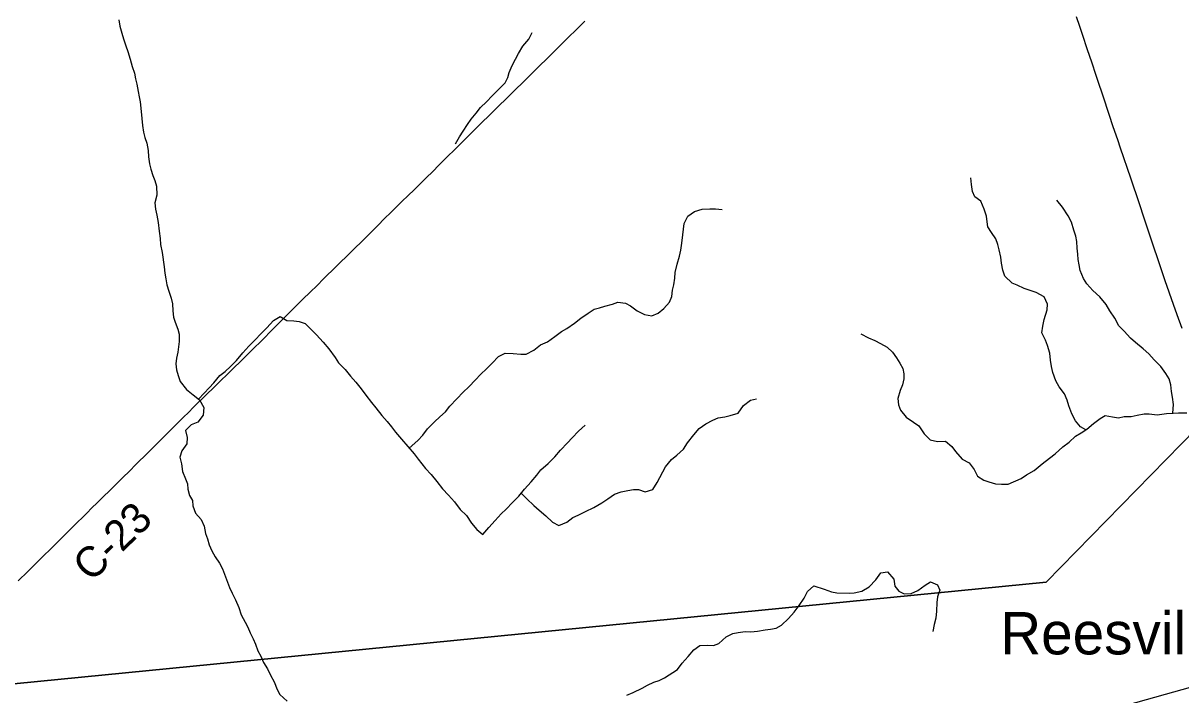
# Model space of a CAD drawing. Extents: x 1442749 to 1756758, y 235267 to 677782.
# Drawn here: x 1623834 to 1635226, y 541852 to 548463 of the extents above; entities that cross this region are included whole.
import ezdxf

# ---------------------------------------------------------------- set-up
doc = ezdxf.new("R2010")
doc.units = 0
for name, color, linetype in [('GM_X_County_Road', 7, 'Continuous'), ('GM_X_County_Road_Text', 7, 'Continuous'), ('GM_X_Major_River', 7, 'Continuous'), ('GM_X_Minor_River', 7, 'Continuous'), ('GM_X_Rail_Line', 7, 'Continuous'), ('GM_X_State_Route', 7, 'Continuous'), ('GM_X_Township', 7, 'Continuous'), ('GM_X_Unincorporated_Text', 7, 'Continuous')]:
    doc.layers.add(name, color=color, linetype=linetype)

msp = doc.modelspace()

# ---------------------------------------------------------------- linework, layer by layer
at = {"layer": 'GM_X_County_Road'}
msp.add_lwpolyline([(1623785, 542973), (1623880, 543067), (1623962, 543148), (1624174, 543358), (1624323, 543506), (1624463, 543644), (1624508, 543689), (1624565, 543744), (1624625, 543803), (1624683, 543861), (1624746, 543922), (1624816, 543991), (1624879, 544054), (1624944, 544118), (1625062, 544234), (1625147, 544319), (1625226, 544398), (1625293, 544466), (1625339, 544513), (1625406, 544578), (1625468, 544639), (1625505, 544676), (1625547, 544718), (1625599, 544768), (1625643, 544811), (1625706, 544873), (1625763, 544929), (1625857, 545021), (1625912, 545075), (1625969, 545131), (1626015, 545176), (1626061, 545222), (1626107, 545267), (1626169, 545328), (1626304, 545465), (1626497, 545657), (1626586, 545745), (1626657, 545814), (1626726, 545882), (1626791, 545946), (1626915, 546069), (1627202, 546351), (1627287, 546436), (1627336, 546485), (1627377, 546526), (1627466, 546613), (1627552, 546697), (1627631, 546775), (1627671, 546814), (1627707, 546850), (1627761, 546902), (1627808, 546948), (1627858, 546997), (1627932, 547071), (1628010, 547149), (1628078, 547216), (1628164, 547300), (1628316, 547451), (1628454, 547587), (1628651, 547781), (1628781, 547910), (1628871, 548000), (1629029, 548153), (1629082, 548206), (1629125, 548249), (1629161, 548285), (1629188, 548312), (1629217, 548340), (1629259, 548381), (1629305, 548426), (1629335, 548456), (1629361, 548483)], dxfattribs=at)
at = {"layer": 'GM_X_Major_River'}
for points in [[(1624774, 548496), (1624784, 548434), (1624805, 548365), (1624821, 548307), (1624845, 548241), (1624863, 548183), (1624888, 548108), (1624906, 548036), (1624928, 547970), (1624939, 547916), (1624953, 547862), (1624967, 547789), (1624976, 547737), (1624984, 547687), (1624996, 547593), (1625001, 547523), (1625007, 547455), (1625017, 547391), (1625030, 547338), (1625050, 547282), (1625064, 547208), (1625067, 547146), (1625077, 547078), (1625091, 547026), (1625110, 546965), (1625130, 546915), (1625146, 546859), (1625149, 546769), (1625129, 546693), (1625135, 546633), (1625148, 546574), (1625162, 546502), (1625174, 546416), (1625181, 546342), (1625187, 546286), (1625202, 546204), (1625222, 546063), (1625229, 546003), (1625237, 545947), (1625249, 545889), (1625266, 545825), (1625290, 545756), (1625302, 545702), (1625308, 545632), (1625315, 545570), (1625331, 545520), (1625355, 545451), (1625368, 545401), (1625370, 545329), (1625357, 545225), (1625343, 545165), (1625337, 545109), (1625342, 545051), (1625358, 544995), (1625378, 544936), (1625442, 544856), (1625507, 544806), (1625569, 544755), (1625613, 544681), (1625605, 544603), (1625552, 544537), (1625486, 544511), (1625431, 544455), (1625447, 544385), (1625445, 544321), (1625394, 544255), (1625376, 544191), (1625391, 544125), (1625403, 544049), (1625433, 543979), (1625450, 543928), (1625456, 543876), (1625470, 543814), (1625500, 543764), (1625505, 543712), (1625531, 543641), (1625587, 543579), (1625614, 543511), (1625628, 543441), (1625648, 543388), (1625664, 543330), (1625689, 543268), (1625723, 543210), (1625767, 543147), (1625795, 543093), (1625816, 543041), (1625846, 542961), (1625866, 542908), (1625890, 542852), (1625923, 542786), (1625955, 542712), (1625979, 542641), (1626018, 542567), (1626044, 542517), (1626068, 542463), (1626098, 542402), (1626119, 542352), (1626143, 542286), (1626173, 542232)], [(1626173, 542232), (1626198, 542170), (1626238, 542109), (1626268, 542047), (1626304, 541981), (1626335, 541904), (1626359, 541854), (1626431, 541790)]]:
    msp.add_lwpolyline(points, dxfattribs=at)
at = {"layer": 'GM_X_Minor_River'}
for points in [[(1628089, 547276), (1628128, 547345), (1628163, 547399), (1628208, 547465), (1628243, 547519), (1628292, 547578), (1628336, 547632), (1628395, 547687), (1628450, 547747), (1628501, 547800), (1628578, 547874), (1628603, 547928), (1628616, 547978), (1628645, 548046), (1628680, 548109), (1628709, 548165), (1628752, 548235), (1628811, 548306), (1628844, 548372)], [(1634291, 544460), (1634239, 544491), (1634189, 544549), (1634154, 544618), (1634123, 544695), (1634109, 544753), (1634080, 544815), (1634029, 544884), (1633995, 544943), (1633966, 545025), (1633955, 545082), (1633945, 545146), (1633936, 545216), (1633913, 545289), (1633894, 545343), (1633858, 545416), (1633869, 545480), (1633882, 545546), (1633911, 545640), (1633914, 545698), (1633881, 545768), (1633801, 545811), (1633733, 545834), (1633683, 545851), (1633617, 545884), (1633565, 545904), (1633495, 545973), (1633476, 546032), (1633463, 546102), (1633455, 546160), (1633440, 546231), (1633425, 546285), (1633407, 546339), (1633362, 546404), (1633326, 546457), (1633319, 546507), (1633314, 546563), (1633290, 546631), (1633259, 546712), (1633199, 546753), (1633176, 546807), (1633167, 546876), (1633160, 546942)], [(1627634, 544279), (1627718, 544355), (1627767, 544407), (1627814, 544469), (1627883, 544538), (1627934, 544588), (1627989, 544639), (1628032, 544693), (1628101, 544764), (1628164, 544830), (1628221, 544885), (1628286, 544951), (1628333, 545004), (1628396, 545064), (1628449, 545115), (1628512, 545181), (1628578, 545214), (1628657, 545211), (1628731, 545204), (1628783, 545204), (1628860, 545243), (1628925, 545297), (1628994, 545326), (1629067, 545379), (1629133, 545427), (1629184, 545458), (1629259, 545511), (1629322, 545559), (1629393, 545610), (1629453, 545648), (1629504, 545661), (1629558, 545677), (1629633, 545696), (1629687, 545717), (1629760, 545708), (1629811, 545680), (1629875, 545631), (1629949, 545594), (1630021, 545583), (1630084, 545608), (1630137, 545654), (1630194, 545718), (1630216, 545771), (1630225, 545834), (1630236, 545886), (1630247, 545952), (1630249, 546010), (1630270, 546092), (1630293, 546168), (1630306, 546228), (1630317, 546298), (1630326, 546380), (1630333, 546434), (1630340, 546492), (1630375, 546562), (1630441, 546609), (1630516, 546633), (1630590, 546634), (1630647, 546637), (1630713, 546630)], [(1635149, 544625), (1635154, 544709), (1635144, 544781), (1635135, 544836), (1635128, 544902), (1635110, 544962), (1635079, 545015), (1635030, 545082), (1634964, 545148), (1634910, 545207), (1634855, 545258), (1634781, 545319), (1634730, 545364), (1634668, 545431), (1634617, 545483), (1634577, 545558), (1634528, 545631), (1634490, 545693), (1634429, 545768), (1634360, 545833), (1634300, 545898), (1634269, 545949), (1634235, 546029), (1634226, 546083), (1634217, 546136), (1634211, 546188), (1634206, 546248), (1634203, 546314), (1634193, 546365), (1634174, 546427), (1634151, 546503), (1634117, 546566), (1634062, 546651), (1634005, 546720)], [(1625560, 544763), (1625615, 544820), (1625665, 544872), (1625710, 544924), (1625769, 544995), (1625822, 545035), (1625873, 545084), (1625934, 545142), (1625997, 545217), (1626056, 545283), (1626121, 545350), (1626170, 545402), (1626231, 545465), (1626298, 545535), (1626363, 545576), (1626429, 545535), (1626499, 545534), (1626549, 545528), (1626609, 545507), (1626665, 545450), (1626722, 545396), (1626786, 545323), (1626843, 545258), (1626903, 545173), (1626938, 545120), (1627002, 545055), (1627055, 544989), (1627109, 544930), (1627160, 544863), (1627205, 544802), (1627261, 544728), (1627306, 544677), (1627364, 544602), (1627415, 544543), (1627459, 544491), (1627498, 544438), (1627556, 544369), (1627619, 544296), (1627681, 544223), (1627722, 544171), (1627793, 544080), (1627849, 544019), (1627904, 543952), (1627960, 543881), (1628019, 543817), (1628079, 543750), (1628136, 543677), (1628198, 543618), (1628247, 543543), (1628298, 543480), (1628358, 543430), (1628417, 543499), (1628478, 543569), (1628537, 543632), (1628588, 543680), (1628651, 543745), (1628712, 543809), (1628769, 543876), (1628832, 543950), (1628889, 544013), (1628928, 544067), (1629001, 544130), (1629066, 544196), (1629121, 544261), (1629190, 544331), (1629237, 544382), (1629300, 544446), (1629365, 544507)], [(1632078, 545406), (1632152, 545367), (1632216, 545338), (1632272, 545311), (1632336, 545274), (1632389, 545226), (1632427, 545169), (1632460, 545118), (1632492, 545064), (1632499, 545012), (1632499, 544962), (1632488, 544902), (1632465, 544848), (1632442, 544770), (1632449, 544707), (1632467, 544653), (1632524, 544586), (1632594, 544537), (1632648, 544499), (1632699, 544420), (1632759, 544361), (1632833, 544344), (1632911, 544349), (1632973, 544296), (1633008, 544246), (1633074, 544173), (1633142, 544134), (1633193, 544069), (1633226, 544005), (1633286, 543964), (1633336, 543947), (1633404, 543930), (1633461, 543926), (1633527, 543927), (1633654, 543982), (1633707, 544017), (1633782, 544059), (1633861, 544124), (1633934, 544183), (1633991, 544223), (1634064, 544294), (1634127, 544340), (1634188, 544397), (1634246, 544430), (1634301, 544466), (1634368, 544521), (1634431, 544573), (1634483, 544600), (1634553, 544587), (1634612, 544579), (1634668, 544590), (1634736, 544593), (1634797, 544605), (1634865, 544618), (1634915, 544618), (1634994, 544609), (1635084, 544620), (1635151, 544625), (1635203, 544626), (1635285, 544629)], [(1628736, 543838), (1628792, 543780), (1628860, 543717), (1628911, 543668), (1628979, 543615), (1629044, 543550), (1629104, 543518), (1629185, 543551), (1629242, 543598), (1629296, 543620), (1629369, 543655), (1629450, 543696), (1629527, 543741), (1629586, 543781), (1629654, 543826), (1629719, 543850), (1629785, 543863), (1629840, 543874), (1629890, 543874), (1629956, 543851), (1630031, 543872), (1630074, 543942), (1630154, 544097), (1630215, 544167), (1630266, 544212), (1630331, 544270), (1630372, 544332), (1630433, 544411), (1630486, 544475), (1630551, 544518), (1630622, 544557), (1630674, 544577), (1630738, 544588), (1630791, 544600), (1630871, 544625), (1630921, 544701), (1630992, 544752), (1631050, 544767)], [(1629773, 541849), (1629838, 541875), (1629927, 541918), (1629979, 541947), (1630040, 541977), (1630092, 541992), (1630145, 542018), (1630272, 542100), (1630319, 542164), (1630378, 542230), (1630433, 542295), (1630492, 542337), (1630567, 542340), (1630627, 542337), (1630679, 542357), (1630752, 542422), (1630819, 542457), (1630869, 542467), (1630940, 542474), (1630996, 542473), (1631060, 542479), (1631135, 542492), (1631187, 542497), (1631244, 542507), (1631298, 542538), (1631367, 542604), (1631422, 542667), (1631469, 542731), (1631520, 542802), (1631551, 542870), (1631614, 542924), (1631718, 542892), (1631790, 542866), (1631840, 542855), (1631963, 542854), (1632013, 542855), (1632088, 542872), (1632159, 542914), (1632224, 542985), (1632273, 543053), (1632339, 543062), (1632401, 542991), (1632412, 542923), (1632451, 542872), (1632503, 542847), (1632574, 542851), (1632638, 542880), (1632711, 542933), (1632764, 542963), (1632832, 542936), (1632853, 542882), (1632832, 542816), (1632826, 542762), (1632821, 542677), (1632814, 542607), (1632799, 542543), (1632786, 542475)]]:
    msp.add_lwpolyline(points, dxfattribs=at)
at = {"layer": 'GM_X_Rail_Line'}
msp.add_lwpolyline([(1622993, 538441), (1624974, 539014), (1626936, 539567), (1628793, 540089), (1634516, 541702), (1636442, 542243), (1638392, 542791), (1640632, 543422), (1643763, 544302), (1646454, 545058), (1646629, 545107), (1646753, 545145), (1646846, 545173), (1646960, 545211), (1647129, 545273), (1647416, 545385), (1647824, 545547)], dxfattribs=at)
at = {"layer": 'GM_X_State_Route'}
msp.add_lwpolyline([(1635238, 545457), (1635190, 545593), (1635153, 545694), (1635073, 545927), (1635022, 546076), (1634937, 546328), (1634865, 546543), (1634819, 546683), (1634733, 546938), (1634632, 547233), (1634605, 547313), (1634560, 547444), (1634520, 547565), (1634461, 547743), (1634409, 547898), (1634392, 547948), (1634349, 548079), (1634309, 548200), (1634257, 548352), (1634231, 548430), (1634199, 548526)], dxfattribs=at)
at = {"layer": 'GM_X_Township'}
for points in [[(1644898, 555254), (1644396, 554944), (1643852, 554569), (1643512, 554247), (1640924, 550208), (1640433, 549458), (1639325, 548457), (1635524, 544621), (1633902, 542962), (1622672, 541854), (1621259, 543594), (1621243, 543613), (1617735, 547931), (1616706, 549187), (1616628, 549233), (1615854, 549688), (1611427, 552129), (1613178, 554457), (1615321, 557320)], [(1653261, 533457), (1649470, 532440), (1648625, 532214), (1643929, 530963), (1641622, 530343), (1638146, 529408), (1628661, 526876), (1619669, 524461), (1619911, 527377), (1620636, 536103), (1621013, 540634), (1621259, 543594), (1622672, 541854), (1633902, 542962), (1635524, 544621), (1639325, 548457), (1640433, 549458), (1640924, 550208), (1643512, 554247), (1643852, 554569), (1644396, 554944), (1644898, 555254)]]:
    msp.add_lwpolyline(points, dxfattribs=at)

# ---------------------------------------------------------------- texts
at = {"layer": 'GM_X_County_Road_Text'}
msp.add_text('C-23', height=300, rotation=44.5176, dxfattribs=at).set_placement((1624504, 542952))
at = {"layer": 'GM_X_Unincorporated_Text'}
msp.add_text('Reesville', height=417, rotation=0, dxfattribs=at).set_placement((1633449, 542250))

doc.saveas('drawing.dxf')
